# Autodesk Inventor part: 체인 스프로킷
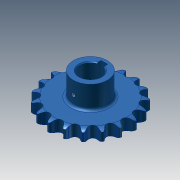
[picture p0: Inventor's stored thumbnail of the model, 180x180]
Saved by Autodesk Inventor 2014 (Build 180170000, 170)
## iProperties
Created: 2014-07
Part Number: 체인 스프로킷
Material: 강
Document SubType Name: Modeling
Designer: KYOUNG IL JANG
Density: 7.85 g/cm^3
Appearance: 하늘색 짙음
Mass: 738.603 g
Surface Area: 236.854 cm^2
Volume: 94.0896 cm^3
CustomPartVersion: 1
Company: 한국ATC센터
Author: KYOUNG IL JANG
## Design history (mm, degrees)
sketch "이론적 톱니 프로파일"
  geometry: L1 (0, 0)-(0, 45.567); L2 (0, 0)-(14.795, 43.098); L3 (0, 45.567)-(14.795, 43.098); L4 (0, 45.567)-(5.661, 50.015); L5 (5.661, 50.015)-(-5.141, 45.406); L6 (-12.428, 43.493)-(-5.573, 46.417); L7 (-5.141, 45.406)-(-5.573, 46.417); L8 (5.573, 46.417)-(5.141, 45.406); L9 (0, 0)-(8.138, 48.771); A1 r 45.567 centre (0, 0) between (0, 45.567) and (14.795, 43.098); A2 r 49.445 centre (0, 0) between (7.302, 48.903) and (-7.302, 48.903); A3 r 4.545 centre (0, 45.567) between (-3.574, 42.758) and (3.574, 42.758); A4 r 7.453 centre (12.428, 43.493) between (7.302, 48.903) and (5.573, 46.417); A5 r 7.453 centre (-12.428, 43.493) between (-5.573, 46.417) and (-7.302, 48.903); A6 r 11.745 centre (5.661, 50.015) between (-5.141, 45.406) and (-3.574, 42.758); A7 r 11.745 centre (-5.661, 50.015) between (3.574, 42.758) and (5.141, 45.406); 2 further points
  constraints: 18 end point, 15 point on circle, 7 centre point, 3 coincident, 3 point on line, 3 symmetric about line, 3 tangent, 1 equal radius, 1 midpoint, 1 parallel, 1 vertical, 1 other
  dimensions: "d0" = 91.13301 diameter of A1 (computed from da_p, da_z); "d2" = 18.9474 deg angle of L2 L1 (computed from da_z); "d3" = 4.545 radius of A3 (= 0.5 x da_Dr + da_SC); "d10" = 128.158 deg angle of L4 L1 (computed from da_z); "d11" = 15.0526 deg angle of L5 L4 (computed from da_z); "d12" = 7.2 distance of L3.start L4.end (= 0.8 x da_Dr); "d13" = 11.745 distance of L4.end L5.end (= 1.3 x da_Dr + da_SC); "d14" = 12.6 distance of A4.centre L1.end (= 1.4 x da_Dr); "d23" = 4.5 distance from line of L9.end L3 (= da_Ha)
sketch "톱니 프로파일"
  geometry: L1 (0, 0)-(0, 45.567); L2 (0, 45.567)-(4.203, 43.837); L3 (0, 45.567)-(-4.203, 43.837); A1 r 4.545 centre (0, 45.567) between (-4.203, 43.837) and (4.203, 43.837); A2 r 22.68 centre (25.176, 35.206) between (7.12, 48.93) and (4.203, 43.837); A3 r 22.68 centre (-25.176, 35.206) between (-4.203, 43.837) and (-7.12, 48.93); A4 r 49.445 centre (0, 0) between (-7.12, 48.93) and (7.12, 48.93) reference; 1 further point
  constraints: 9 point on circle, 6 end point, 3 centre point, 2 tangent, 1 coincident, 1 equal radius, 1 vertical, 1 other
  dimensions: "d44" = 135.263 deg angle of L3 L2 (= da_Alfa); "d45" = 22.68 radius of A2 (= da_Re); "d46" = 4.545 radius of A1 (= da_Ri)
sketch "단면 프로파일"
  geometry: L1 (49.445, 0)-(-49.445, 0) reference; L2 (33.265, 6.65)-(-33.265, 6.65); L3 (-33.265, 6.65)-(-33.265, -6.65); L4 (-33.265, -6.65)-(33.265, -6.65); L5 (33.265, -6.65)-(33.265, 6.65); L6 (33.265, 6.65)-(49.445, 6.65); L7 (49.445, 6.65)-(49.445, -6.65); L8 (49.445, -6.65)-(33.265, -6.65); L9 (33.265, -6.65)-(33.265, 6.65); L10 (42.183, 6.65)-(0, 6.65); L11 (0, 6.65)-(0, -6.65); L12 (0, -6.65)-(42.183, -6.65); L13 (0, 6.65)-(0, -6.65); L14 (49.445, 4.775)-(49.445, -4.775); A1 r 15 centre (42.183, -8.35) between (49.445, 4.775) and (42.183, 6.65); A2 r 15 centre (42.183, 8.35) between (42.183, -6.65) and (49.445, -4.775); 2 further points
  constraints: 26 end point, 7 midpoint, 5 perpendicular, 4 parallel, 4 point on circle, 3 point on line, 3 symmetric about line, 2 centre point, 2 horizontal, 2 tangent, 1 collinear, 1 other
  dimensions: "d30" = 13.3 distance between parallel lines of L8 L6 (= da_Bf); "d31" = 66.53007 distance between parallel lines of L3 L5 (= da_Ds); "d32" = 13.3 distance between parallel lines of L4 L2 (= da_Bs); "d33" = 1.875 distance from line of L14.start L6 (= da_Ba); "d34" = 15 radius of A1 (= da_Rx); "d43" = 6.65 distance between parallel lines of L4 L1 (computed from da_k, da_pt, da_Bs)
revolve "슈라우드" stored, may be unused: angle "d36" = 90 deg
revolve "스트랜드" stored, may be unused: angle "d37" = 90 deg
extrude "이론적 톱니" cut sketch "이론적 톱니 프로파일" stored distance "d18" = 10; taper "d19" = 0 deg; dims "d49" = 0, "form_type" = 0 [user parameter]
extrude "톱니" cut sketch "톱니 프로파일" stored distance "d47" = 10; taper "d48" = 0 deg; dims "d50" = 10, "form_type" = 0 [user parameter]
node "타이밍 평면"
node "작업 평면3"
sketch "스케치5"
  geometry: C1 r 20 at (0, -45.567); 1 further point
  constraints: 1 centre point, 1 coincident
  dimensions: "d52" = 40 diameter of C1
extrude "돌출4" join sketch "스케치5" stored distance "d53" = 10; taper "d54" = 0 deg
sketch "스케치6"
  geometry: L1 (4, 11.843)-(4, 16.5); L2 (4, 16.5)-(-4, 16.5); L3 (-4, 16.5)-(-4, 11.843); A1 r 12.5 centre (0, 0) between (4, 11.843) and (-4, 11.843); 1 further point
  constraints: 6 end point, 2 parallel, 2 point on circle, 1 centre point, 1 coincident, 1 perpendicular, 1 vertical
  dimensions: "d55" = 25 diameter of A1; "d56" = 29 dimension on A1 L2 (computed from d55); "d57" = 8 distance of L1.end L2.end
extrude "돌출5" cut sketch "스케치6" stored distance "d58" = 10; taper "d59" = 0 deg
fillet "모깎기2" dims "d60" = 3
chamfer "모따기1" distance "d61" = 1; stored, may be unused: second distance "d62" = 2, angle "d63" = 45 deg
node "작업 평면4"
sketch "스케치7"
  geometry: L1 (-13.5, -13.3)-(13.5, -13.3) reference; 4 further points
  constraints: 1 vertical alignment
  dimensions: "d65" = 25 distance from line of point (0, 11.7) L1
hole "구멍1" sketch "스케치7" at (0, 11.7) diameter "d66" = 4.134; stored, may be unused: countersink angle "d70" = 90 deg, drill point angle "d72" = 118 deg; dims "d67" = 6, "d68" = 4, "d69" = 2, "d71" = 8
body "Solid1"
pattern_linear "스트랜드 패턴" dims "d40" = 24 (= da_pt)
pattern_circular "톱니 패턴" dims angle "d21" = 360 deg
other parameters: "da_p" = 15 [user parameter; used in 1 equation term], "da_Dr" = 9 [user parameter; used in 4 equation terms], "da_SC" = 0.045 [user parameter; used in 2 equation terms], "da_Ha" = 4.5 [user parameter; used in 1 equation term], "da_pt" = 24 [user parameter; used in 2 equation terms], "da_Bf" = 13.3 [user parameter; used in 1 equation term], "d28" = 0, "d29" = 0, "da_Ba" = 1.875 [user parameter; used in 1 equation term], "da_Rx" = 15 [user parameter; used in 1 equation term], "da_Ra" = 0.6 [user parameter], "da_Bs" = 13.3 [user parameter; used in 2 equation terms], "da_Ds" = 66.53007 [user parameter; used in 1 equation term], "d42" = 0, "da_Re" = 22.68 [user parameter; used in 1 equation term], "da_Ri" = 4.545 [user parameter; used in 1 equation term], "da_Alfa" = 135.263 deg [user parameter; used in 1 equation term]
